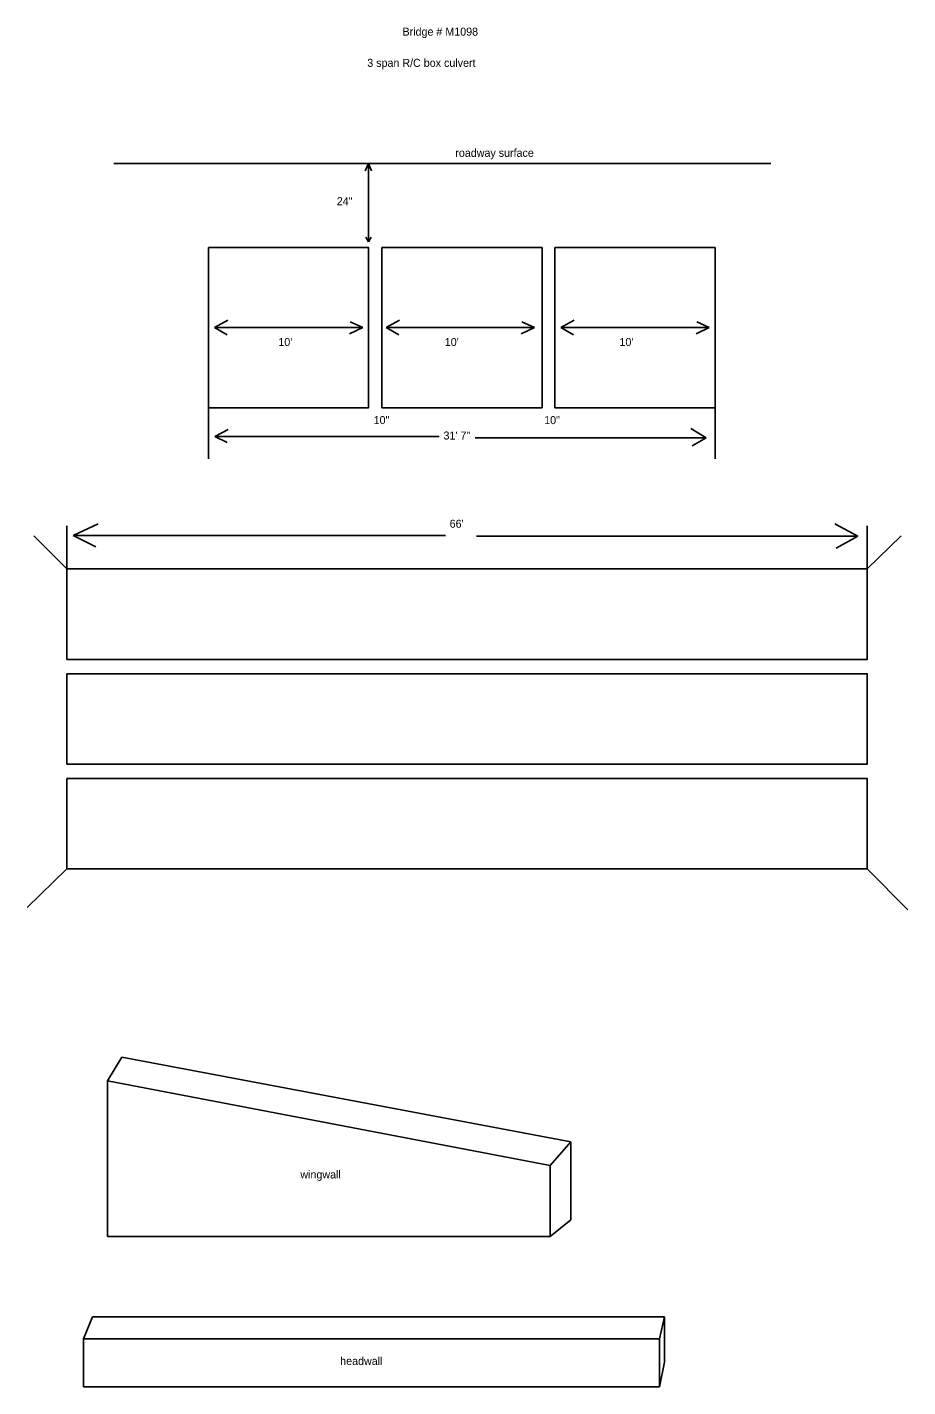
# Model space of a CAD drawing. Extents: x -629.7 to -574.7, y -353.6 to -268.6.
import ezdxf

# ---------------------------------------------------------------- set-up
doc = ezdxf.new("R2010")
doc.units = 0
doc.layers.add('Default', color=7, linetype='Continuous')

msp = doc.modelspace()

# ---------------------------------------------------------------- linework, layer by layer
at = {"layer": 'Default'}
for p, q in [((-608.404, -277.151), (-624.314, -277.151)), ((-608.404, -277.151), (-608.621, -277.594)), ((-608.404, -277.151), (-608.404, -281.469)), ((-608.404, -277.151), (-608.215, -277.605)), ((-608.404, -277.151), (-593.023, -277.151)), ((-593.023, -277.151), (-583.278, -277.151)), ((-608.404, -282.033), (-608.568, -281.752)), ((-608.404, -281.469), (-608.404, -282.033)), ((-608.404, -282.033), (-608.23, -281.752)), ((-618.035, -287.395), (-617.196, -286.924)), ((-608.765, -287.395), (-609.543, -287.047)), ((-607.312, -287.395), (-606.473, -286.924)), ((-598.042, -287.395), (-598.82, -287.047)), ((-596.39, -287.395), (-595.551, -286.924)), ((-587.12, -287.395), (-587.898, -287.047)), ((-618.035, -287.395), (-608.765, -287.395)), ((-618.035, -287.395), (-617.237, -287.845)), ((-608.765, -287.395), (-609.584, -287.784)), ((-607.312, -287.395), (-598.042, -287.395)), ((-607.312, -287.395), (-606.514, -287.845)), ((-598.042, -287.395), (-598.861, -287.784)), ((-596.39, -287.395), (-587.12, -287.395)), ((-596.39, -287.395), (-595.592, -287.845)), ((-587.12, -287.395), (-587.938, -287.784)), ((-618.404, -292.401), (-618.404, -295.589)), ((-586.759, -292.401), (-586.759, -295.589)), ((-618.014, -294.203), (-617.165, -293.767)), ((-587.319, -294.287), (-588.262, -293.706)), ((-618.014, -294.203), (-603.988, -294.203)), ((-618.014, -294.203), (-617.227, -294.576)), ((-601.749, -294.287), (-587.319, -294.287)), ((-587.319, -294.287), (-588.189, -294.794)), ((-627.248, -302.481), (-627.248, -299.775)), ((-626.864, -300.384), (-625.289, -299.667)), ((-577.839, -300.42), (-579.271, -299.667)), ((-577.248, -302.481), (-577.248, -299.775)), ((-627.248, -302.481), (-629.318, -300.418)), ((-603.587, -300.384), (-626.864, -300.384)), ((-626.864, -300.384), (-625.432, -301.1)), ((-601.653, -300.42), (-577.839, -300.42)), ((-577.839, -300.42), (-579.199, -301.172)), ((-577.248, -302.481), (-575.141, -300.418)), ((-627.248, -321.221), (-629.727, -323.642)), ((-577.248, -321.221), (-574.717, -323.769)), ((-624.713, -334.467), (-623.805, -332.984)), ((-623.805, -332.984), (-595.776, -338.273)), ((-624.713, -334.467), (-624.713, -344.186)), ((-624.713, -334.467), (-597.056, -339.743)), ((-597.056, -339.743), (-595.776, -338.273)), ((-595.776, -338.273), (-595.776, -343.139)), ((-597.056, -344.186), (-597.056, -339.743)), ((-597.056, -344.186), (-595.776, -343.139)), ((-624.713, -344.186), (-597.056, -344.186)), ((-626.212, -350.582), (-625.644, -349.207)), ((-625.644, -349.207), (-589.913, -349.207)), ((-590.23, -350.582), (-589.913, -349.207)), ((-589.913, -349.207), (-589.913, -349.207)), ((-589.913, -349.207), (-589.913, -352.038)), ((-626.212, -350.582), (-590.23, -350.582)), ((-626.212, -350.582), (-626.212, -353.582)), ((-590.23, -350.582), (-590.23, -353.582)), ((-589.913, -352.038), (-590.23, -353.582)), ((-626.212, -353.582), (-590.23, -353.582))]:
    msp.add_line(p, q, dxfattribs=at)
for points in [[(-618.404, -282.401), (-608.404, -282.401), (-608.404, -292.401), (-618.404, -292.401)], [(-607.564, -282.401), (-597.564, -282.401), (-597.564, -292.401), (-607.564, -292.401)], [(-596.759, -282.401), (-586.759, -282.401), (-586.759, -292.401), (-596.759, -292.401)], [(-627.248, -302.481), (-577.248, -302.481), (-577.248, -308.127), (-627.248, -308.127)], [(-627.248, -309.026), (-577.248, -309.026), (-577.248, -314.672), (-627.248, -314.672)], [(-627.248, -315.575), (-577.248, -315.575), (-577.248, -321.221), (-627.248, -321.221)]]:
    msp.add_lwpolyline(points, close=True, dxfattribs=at)

# ---------------------------------------------------------------- texts
for s, p in [('Bridge # M1098', (-606.282, -269.153)), ('3 span R/C box culvert', (-608.484, -271.104)), ('roadway surface', (-602.983, -276.727)), ('24"', (-610.389, -279.749)), ("10'", (-614.037, -288.547)), ("10'", (-603.641, -288.547)), ("10'", (-592.73, -288.547)), ("10'", (-592.73, -288.547)), ('10"', (-608.085, -293.428)), ('10"', (-597.432, -293.428)), ('31\' 7"', (-603.721, -294.391)), ("66'", (-603.337, -299.903)), ('wingwall', (-612.663, -340.563)), ('headwall', (-610.175, -352.218))]:
    msp.add_text(s, height=0.5, dxfattribs=at).set_placement(p)

doc.saveas('drawing.dxf')
